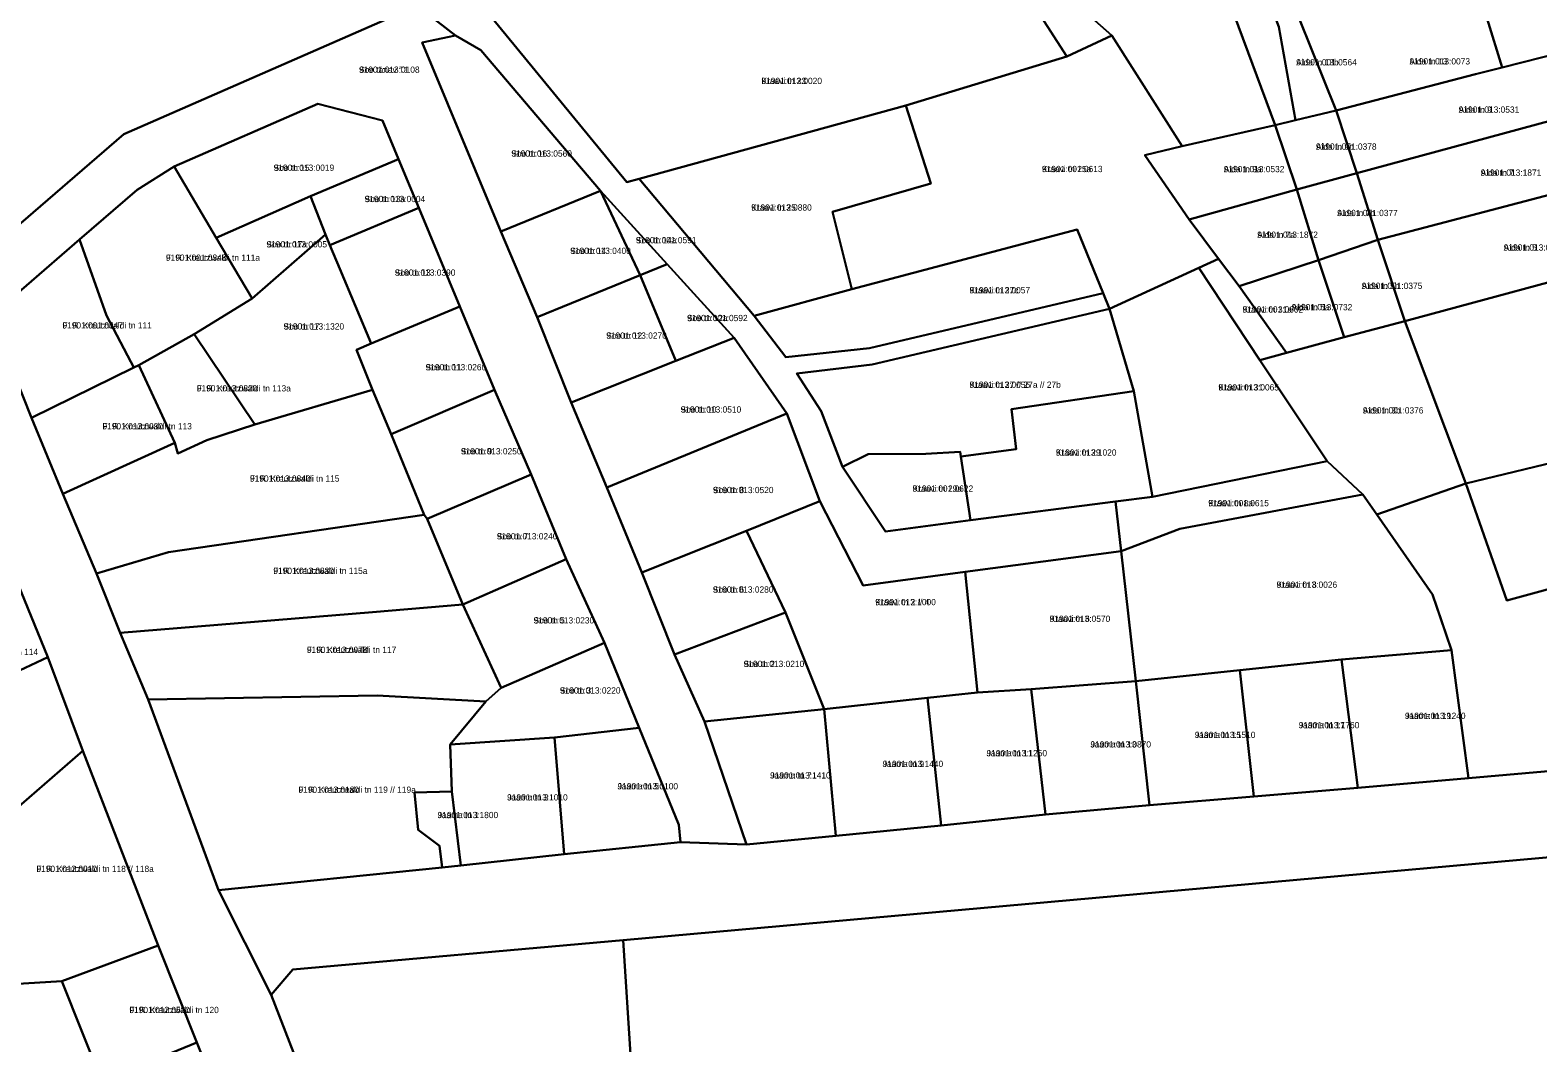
# Model space of a CAD drawing. Extents: x 675810 to 681273, y 6411190 to 6417565.
# Drawn here: x 678840.3 to 679201.2, y 6413542.7 to 6413785.2 of the extents above; entities that cross this region are included whole.
import ezdxf

# ---------------------------------------------------------------- set-up
doc = ezdxf.new("R2010")
doc.units = 0
for name, color, linetype in [('L_AADRESS', 7, 'Continuous'), ('PIIR', 7, 'Continuous'), ('TUNNUS', 7, 'Continuous')]:
    doc.layers.add(name, color=color, linetype=linetype)

msp = doc.modelspace()

# ---------------------------------------------------------------- linework, layer by layer
at = {"layer": 'PIIR'}
for points in [[(678826.29, 6413728.84), (678795.17, 6413816.56), (678828, 6413829.05), (678859.96, 6413845.39), (678877.6, 6413860.64), (678932.91, 6413791.06), (678862.71, 6413760.35)], [(679063.55, 6413813.47), (679076.05, 6413804.42), (679099.24, 6413783.96), (679088.47, 6413778.92), (679077.61, 6413795.82)], [(679076.05, 6413804.42), (679124.13, 6413800.75), (679138.31, 6413762.5), (679116.06, 6413757.41), (679099.24, 6413783.96)], [(679124.13, 6413800.75), (679133.81, 6413800.32), (679139.23, 6413785.98), (679143.23, 6413763.68), (679138.31, 6413762.5)], [(679139.17, 6413800.08), (679144.1, 6413788.04), (679152.9, 6413765.99), (679143.23, 6413763.68), (679139.23, 6413785.98), (679133.81, 6413800.32)], [(679139.17, 6413800.08), (679200.86, 6413799.83), (679207.07, 6413779.92), (679192.67, 6413776.28), (679189.1, 6413787.94), (679180.37, 6413787.89), (679144.1, 6413788.04)], [(678948, 6413791.61), (679001.31, 6413793.35), (679077.61, 6413795.82), (679088.47, 6413778.92), (679049.95, 6413767.16), (678986.06, 6413749.64), (678983.09, 6413748.82)], [(679144.1, 6413788.04), (679180.37, 6413787.89), (679189.1, 6413787.94), (679192.67, 6413776.28), (679186.28, 6413774.66), (679152.9, 6413765.99)], [(678976.85, 6413746.77), (678952.97, 6413737), (678934.1, 6413782.23), (678942.15, 6413783.91), (678948.14, 6413780.47)], [(679117.74, 6413739.91), (679124.79, 6413730.47), (679120.02, 6413728.32), (679098.68, 6413718.49), (679097.14, 6413722.24), (679090.92, 6413737.49), (679037.01, 6413723.19), (679032.32, 6413741.72), (679055.93, 6413748.54), (679049.95, 6413767.16), (679088.47, 6413778.92), (679099.24, 6413783.96), (679116.06, 6413757.41), (679107.12, 6413755.3)], [(679152.9, 6413765.99), (679186.28, 6413774.66), (679192.67, 6413776.28), (679207.07, 6413779.92), (679212.4, 6413765.71), (679157.89, 6413750.98)], [(678909.17, 6413767.57), (678924.61, 6413763.6), (678928.45, 6413754.37), (678907.43, 6413745.44), (678884.86, 6413735.51), (678874.73, 6413752.61)], [(678986.06, 6413749.64), (679049.95, 6413767.16), (679055.93, 6413748.54), (679032.32, 6413741.72), (679037.01, 6413723.19), (679013.58, 6413716.85)], [(679138.31, 6413762.5), (679143.23, 6413763.68), (679152.9, 6413765.99), (679157.89, 6413750.98), (679143.48, 6413747.11)], [(679212.4, 6413765.71), (679217.3, 6413749.31), (679162.87, 6413735.01), (679157.89, 6413750.98)], [(679143.48, 6413747.11), (679117.74, 6413739.91), (679107.12, 6413755.3), (679116.06, 6413757.41), (679138.31, 6413762.5)], [(678928.45, 6413754.37), (678933.3, 6413742.71), (678912.07, 6413733.74), (678911.01, 6413736.28), (678907.43, 6413745.44)], [(678858.59, 6413716.93), (678852.13, 6413735.1), (678865.9, 6413746.98), (678874.73, 6413752.61), (678884.86, 6413735.51), (678893.45, 6413720.95), (678879.58, 6413712.42), (678866.3, 6413705.02), (678865.15, 6413704.45), (678864.43, 6413705.82)], [(679143.48, 6413747.11), (679157.89, 6413750.98), (679162.87, 6413735.01), (679148.72, 6413730.16)], [(678976.85, 6413746.77), (678986.29, 6413726.59), (678961.65, 6413716.54), (678952.97, 6413737)], [(678986.29, 6413726.59), (678976.85, 6413746.77), (678992.77, 6413729.23)], [(679143.48, 6413747.11), (679148.72, 6413730.16), (679129.69, 6413723.9), (679124.79, 6413730.47), (679117.74, 6413739.91)], [(679162.87, 6413735.01), (679217.3, 6413749.31), (679223.07, 6413730.04), (679169.39, 6413715.58)], [(678907.43, 6413745.44), (678911.01, 6413736.28), (678893.45, 6413720.95), (678884.86, 6413735.51)], [(678921.91, 6413710.19), (678914.45, 6413728.04), (678912.07, 6413733.74), (678933.3, 6413742.71), (678943.12, 6413719.07)], [(678894.06, 6413690.79), (678879.58, 6413712.42), (678893.45, 6413720.95), (678911.01, 6413736.28), (678912.07, 6413733.74), (678914.45, 6413728.04), (678921.91, 6413710.19), (678918.45, 6413708.68), (678922.27, 6413699.08)], [(679013.58, 6413716.85), (679037.01, 6413723.19), (679090.92, 6413737.49), (679097.14, 6413722.24), (679041.18, 6413709.07), (679021.21, 6413706.91)], [(678840.61, 6413692.4), (678830.89, 6413716.75), (678852.13, 6413735.1), (678858.59, 6413716.93), (678864.43, 6413705.82), (678865.15, 6413704.45)], [(679148.72, 6413730.16), (679162.87, 6413735.01), (679169.39, 6413715.58), (679154.88, 6413711.69)], [(678986.29, 6413726.59), (678992.77, 6413729.23), (679008.79, 6413711.58), (678994.88, 6413706.06)], [(679120.02, 6413728.32), (679124.79, 6413730.47), (679129.69, 6413723.9), (679141.04, 6413707.94), (679134.68, 6413706.23)], [(679154.88, 6413711.69), (679141.04, 6413707.94), (679129.69, 6413723.9), (679148.72, 6413730.16)], [(679223.07, 6413730.04), (679235.52, 6413689.16), (679183.96, 6413676.67), (679169.39, 6413715.58)], [(678969.79, 6413696.09), (678961.65, 6413716.54), (678986.29, 6413726.59), (678994.88, 6413706.06)], [(679120.02, 6413728.32), (679134.68, 6413706.23), (679150.77, 6413682), (679108.94, 6413673.45), (679104.53, 6413698.78), (679098.68, 6413718.49)], [(678951.45, 6413699.09), (678926.73, 6413688.45), (678922.27, 6413699.08), (678918.45, 6413708.68), (678921.91, 6413710.19), (678943.12, 6413719.07)], [(679023.81, 6413703.04), (679041.85, 6413705.13), (679098.68, 6413718.49), (679104.53, 6413698.78), (679075.22, 6413694.49), (679076.29, 6413684.93), (679063.09, 6413683.16), (679062.94, 6413684.22), (679054.68, 6413683.75), (679040.92, 6413683.71), (679034.72, 6413680.68), (679029.61, 6413694.02)], [(679154.88, 6413711.69), (679169.39, 6413715.58), (679183.96, 6413676.67), (679162.66, 6413669.25), (679159.3, 6413674.02), (679150.77, 6413682), (679134.68, 6413706.23), (679141.04, 6413707.94)], [(678874.95, 6413686.38), (678866.3, 6413705.02), (678879.58, 6413712.42), (678894.06, 6413690.79), (678882.56, 6413687.02), (678875.62, 6413683.83)], [(679008.79, 6413711.58), (679021.39, 6413693.4), (678978.31, 6413675.73), (678969.79, 6413696.09), (678994.88, 6413706.06)], [(678840.61, 6413692.4), (678865.15, 6413704.45), (678866.3, 6413705.02), (678874.95, 6413686.38), (678848.13, 6413674.24)], [(678856.15, 6413655.14), (678848.13, 6413674.24), (678874.95, 6413686.38), (678875.62, 6413683.83), (678882.56, 6413687.02), (678894.06, 6413690.79), (678922.27, 6413699.08), (678926.73, 6413688.45), (678934.63, 6413669.18), (678873.41, 6413660.22)], [(678935.36, 6413668.19), (678934.63, 6413669.18), (678926.73, 6413688.45), (678951.45, 6413699.09), (678960.19, 6413678.87)], [(679065.38, 6413667.91), (679063.09, 6413683.16), (679076.29, 6413684.93), (679075.22, 6413694.49), (679104.53, 6413698.78), (679108.94, 6413673.45), (679100.14, 6413672.34)], [(678978.31, 6413675.73), (679021.39, 6413693.4), (679029.36, 6413672.42), (679011.74, 6413665.37), (678986.68, 6413655.34)], [(679215.96, 6413660.7), (679217.77, 6413655.18), (679193.81, 6413648.7), (679183.96, 6413676.67), (679235.52, 6413689.16), (679243.75, 6413664.08)], [(679065.38, 6413667.91), (679045.07, 6413665.2), (679034.72, 6413680.68), (679040.92, 6413683.71), (679054.68, 6413683.75), (679062.94, 6413684.22), (679063.09, 6413683.16)], [(679115.48, 6413665.83), (679101.49, 6413660.46), (679100.14, 6413672.34), (679108.94, 6413673.45), (679150.77, 6413682), (679159.3, 6413674.02)], [(678960.19, 6413678.87), (678968.58, 6413658.56), (678943.85, 6413647.72), (678935.36, 6413668.19)], [(679193.81, 6413648.7), (679217.77, 6413655.18), (679215.96, 6413660.7), (679243.75, 6413664.08), (679249.72, 6413644.17), (679220.83, 6413641.03), (679228.23, 6413609.96), (679184.59, 6413606.09), (679180.54, 6413636.74), (679177.8, 6413644.75), (679175.98, 6413650.08), (679162.66, 6413669.25), (679183.96, 6413676.67)], [(679039.72, 6413652.22), (679064.09, 6413655.49), (679067.03, 6413626.65), (679055.08, 6413625.34), (679030.33, 6413622.63), (679021.13, 6413645.8), (679011.74, 6413665.37), (679029.36, 6413672.42)], [(679101.49, 6413660.46), (679115.48, 6413665.83), (679159.3, 6413674.02), (679162.66, 6413669.25), (679175.98, 6413650.08), (679180.54, 6413636.74), (679154.21, 6413634.56), (679129.83, 6413632), (679105, 6413629.38)], [(678856.15, 6413655.14), (678873.41, 6413660.22), (678934.63, 6413669.18), (678935.36, 6413668.19), (678943.85, 6413647.72), (678922.25, 6413645.87), (678861.84, 6413640.88)], [(678986.68, 6413655.34), (679011.74, 6413665.37), (679021.13, 6413645.8), (678994.52, 6413635.71)], [(679105, 6413629.38), (679079.92, 6413627.45), (679067.03, 6413626.65), (679064.09, 6413655.49), (679101.49, 6413660.46)], [(678943.85, 6413647.72), (678968.58, 6413658.56), (678977.75, 6413638.55), (678953.06, 6413627.76)], [(678796.59, 6413635.26), (678836.58, 6413654.64), (678844.5, 6413635.09), (678805.1, 6413616.54)], [(678943.85, 6413647.72), (678953.06, 6413627.76), (678949.36, 6413624.48), (678923.35, 6413625.95), (678868.51, 6413624.93), (678861.84, 6413640.88), (678922.25, 6413645.87)], [(678994.52, 6413635.71), (679021.13, 6413645.8), (679030.33, 6413622.63), (679001.7, 6413619.65)], [(678940.81, 6413614.2), (678949.36, 6413624.48), (678953.06, 6413627.76), (678977.75, 6413638.55), (678986.11, 6413618.2), (678965.8, 6413615.87)], [(678852.91, 6413612.7), (678810.65, 6413575.98), (678800.26, 6413567.02), (678763.72, 6413543), (678719.84, 6413576.34), (678764.11, 6413597.24), (678805.1, 6413616.54), (678844.5, 6413635.09)], [(679129.83, 6413632), (679154.21, 6413634.56), (679158.11, 6413603.82), (679133.18, 6413601.75)], [(679158.11, 6413603.82), (679154.21, 6413634.56), (679180.54, 6413636.74), (679184.59, 6413606.09)], [(679105, 6413629.38), (679129.83, 6413632), (679133.18, 6413601.75), (679108.27, 6413599.69)], [(679058.38, 6413594.81), (679055.08, 6413625.34), (679067.03, 6413626.65), (679079.92, 6413627.45), (679083.36, 6413597.41)], [(679105, 6413629.38), (679108.27, 6413599.69), (679083.36, 6413597.41), (679079.92, 6413627.45)], [(678868.51, 6413624.93), (678923.35, 6413625.95), (678949.36, 6413624.48), (678940.81, 6413614.2), (678941.27, 6413602.94), (678932.27, 6413602.69), (678933.21, 6413593.73), (678938.27, 6413589.92), (678938.95, 6413584.75), (678885.41, 6413579.27)], [(679055.08, 6413625.34), (679058.38, 6413594.81), (679033.13, 6413592.31), (679030.33, 6413622.63)], [(679001.7, 6413619.65), (679030.33, 6413622.63), (679033.13, 6413592.31), (679011.76, 6413590.25)], [(678965.8, 6413615.87), (678986.11, 6413618.2), (678995.58, 6413594.92), (678995.96, 6413590.79), (678968.13, 6413587.95)], [(678943.38, 6413585.24), (678941.27, 6413602.94), (678940.81, 6413614.2), (678965.8, 6413615.87), (678968.13, 6413587.95)], [(678870.9, 6413566.06), (678847.87, 6413557.53), (678800.48, 6413554.63), (678800.26, 6413567.02), (678810.65, 6413575.98), (678852.91, 6413612.7)], [(678665.74, 6413606.8), (678695.3, 6413600.11), (678714.53, 6413595.62), (678719.84, 6413576.34), (678763.72, 6413543), (678800.26, 6413567.02), (678800.48, 6413554.63), (678847.87, 6413557.53), (678857.44, 6413533.51), (678880.23, 6413542.83), (678888.05, 6413523.44), (678805.9, 6413512.49), (678631.5, 6413551.06), (678639.57, 6413556.01), (678656.18, 6413588.23)], [(678932.27, 6413602.69), (678941.27, 6413602.94), (678943.38, 6413585.24), (678938.95, 6413584.75), (678938.27, 6413589.92), (678933.21, 6413593.73)], [(678870.9, 6413566.06), (678880.23, 6413542.83), (678857.44, 6413533.51), (678847.87, 6413557.53)], [(678914.04, 6413512.86), (678897.96, 6413554.23), (678903.14, 6413560.3), (678982.22, 6413567.37), (678984.06, 6413538.75), (678963.55, 6413537.52), (678965.52, 6413517.11)]]:
    msp.add_lwpolyline(points, close=True, dxfattribs=at)
for points in [[(678826.29, 6413728.84), (678862.71, 6413760.35), (678932.91, 6413791.06), (678942.15, 6413783.91), (678934.1, 6413782.23), (678952.97, 6413737), (678961.65, 6413716.54), (678969.79, 6413696.09), (678978.31, 6413675.73), (678986.68, 6413655.34), (678994.52, 6413635.71), (679001.7, 6413619.65), (679011.76, 6413590.25), (678995.96, 6413590.79), (678995.58, 6413594.92), (678986.11, 6413618.2), (678977.75, 6413638.55), (678968.58, 6413658.56), (678960.19, 6413678.87), (678951.45, 6413699.09), (678943.12, 6413719.07), (678933.3, 6413742.71), (678928.45, 6413754.37), (678924.61, 6413763.6), (678909.17, 6413767.57), (678874.73, 6413752.61), (678865.9, 6413746.98), (678852.13, 6413735.1), (678830.89, 6413716.75)], [(678948, 6413791.61), (678983.09, 6413748.82), (678986.06, 6413749.64), (679013.58, 6413716.85), (679021.21, 6413706.91), (679041.18, 6413709.07), (679097.14, 6413722.24), (679098.68, 6413718.49), (679041.85, 6413705.13), (679023.81, 6413703.04), (679029.61, 6413694.02), (679034.72, 6413680.68), (679045.07, 6413665.2), (679065.38, 6413667.91), (679100.14, 6413672.34), (679101.49, 6413660.46), (679064.09, 6413655.49), (679039.72, 6413652.22), (679029.36, 6413672.42), (679021.39, 6413693.4), (679008.79, 6413711.58), (678992.77, 6413729.23), (678976.85, 6413746.77), (678948.14, 6413780.47), (678942.15, 6413783.91), (678932.91, 6413791.06)], [(678830.89, 6413716.75), (678840.61, 6413692.4), (678848.13, 6413674.24), (678856.15, 6413655.14), (678861.84, 6413640.88), (678868.51, 6413624.93), (678885.41, 6413579.27), (678897.96, 6413554.23), (678914.04, 6413512.86)], [(678888.05, 6413523.44), (678880.23, 6413542.83), (678870.9, 6413566.06), (678852.91, 6413612.7), (678844.5, 6413635.09), (678836.58, 6413654.64)], [(679314.57, 6413597.1), (678982.22, 6413567.37), (678903.14, 6413560.3), (678897.96, 6413554.23), (678885.41, 6413579.27), (678938.95, 6413584.75), (678943.38, 6413585.24), (678968.13, 6413587.95), (678995.96, 6413590.79), (679011.76, 6413590.25), (679033.13, 6413592.31), (679058.38, 6413594.81), (679083.36, 6413597.41), (679108.27, 6413599.69), (679133.18, 6413601.75), (679158.11, 6413603.82), (679184.59, 6413606.09), (679228.23, 6413609.96)], [(678984.06, 6413538.75), (678982.22, 6413567.37), (679314.57, 6413597.1), (679330.12, 6413556.83), (679423.93, 6413564.22)]]:
    msp.add_lwpolyline(points, dxfattribs=at)

# ---------------------------------------------------------------- texts
at = {"layer": 'L_AADRESS'}
for s, p in [('Soo tänav T1', (678919.02, 6413775.01)), ('Aida tn 13b', (679143.36, 6413776.78)), ('Aida tn 13', (679170.47, 6413777.01)), ('Kraavi tn 23', (679015.34, 6413772.32)), ('Aida tn 9', (679182.26, 6413765.45)), ('Aida tn 9b', (679148.1, 6413756.6)), ('Soo tn 16', (678955.48, 6413754.94)), ('Soo tn 15', (678898.58, 6413751.54)), ('Kraavi tn 25a', (679082.5, 6413751.23)), ('Aida tn 9a', (679126.03, 6413751.21)), ('Aida tn 7', (679187.53, 6413750.36)), ('Soo tn 13a', (678920.36, 6413744.05)), ('Kraavi tn 25', (679012.89, 6413742.01)), ('Aida tn 7b', (679153.17, 6413740.7)), ('Soo tn 14a', (678985.3, 6413734.2)), ('Aida tn 7a', (679134.05, 6413735.5)), ('Soo tn 17a', (678896.85, 6413733.2)), ('Soo tn 14', (678969.58, 6413731.65)), ('Aida tn 5', (679193.04, 6413732.44)), ('F. R. Kreutzwaldi tn 111a', (678872.79, 6413730)), ('Soo tn 13', (678927.59, 6413726.43)), ('Aida tn 5b', (679159.05, 6413723.26)), ('Kraavi tn 27c', (679065.16, 6413722.2)), ('Kraavi tn 31a', (679130.53, 6413717.6)), ('Aida tn 5a', (679142.29, 6413718.16)), ('F. R. Kreutzwaldi tn 111', (678848.02, 6413713.79)), ('Soo tn 17', (678900.95, 6413713.54)), ('Soo tn 12a', (678997.54, 6413715.55)), ('Soo tn 12', (678978.2, 6413711.34)), ('Soo tn 11', (678934.96, 6413703.76)), ('F. R. Kreutzwaldi tn 113a', (678880.18, 6413698.72)), ('Kraavi tn 27 // 27a // 27b', (679065.16, 6413699.58)), ('Kraavi tn 31', (679124.73, 6413698.95)), ('Soo tn 10', (678996.01, 6413693.65)), ('Aida tn 3b', (679159.32, 6413693.44)), ('F. R. Kreutzwaldi tn 113', (678857.6, 6413689.63)), ('Soo tn 9', (678943.42, 6413683.64)), ('Kraavi tn 29', (679085.84, 6413683.35)), ('F. R. Kreutzwaldi tn 115', (678892.92, 6413677.11)), ('Soo tn 8', (679003.74, 6413674.37)), ('Kraavi tn 29a', (679051.54, 6413674.71)), ('Kraavi tn 8a', (679122.32, 6413671.23)), ('Soo tn 7', (678952.01, 6413663.29)), ('F. R. Kreutzwaldi tn 115a', (678898.51, 6413655.03)), ('Kraavi tn 8', (679138.67, 6413651.7)), ('Soo tn 6', (679003.73, 6413650.54)), ('Kraavi tn 2 // 4', (679042.6, 6413647.53)), ('Soo tn 5', (678960.8, 6413643.16)), ('Kraavi tn 6', (679084.35, 6413643.55)), ('F. R. Kreutzwaldi tn 114', (678820.78, 6413635.59)), ('F. R. Kreutzwaldi tn 117', (678906.53, 6413636.1)), ('Soo tn 2', (679011.09, 6413632.73)), ('Soo tn 3', (678967.12, 6413626.38)), ('Jaama tn 19', (679169.4, 6413620.3)), ('Jaama tn 15', (679119.09, 6413615.73)), ('Jaama tn 17', (679143.97, 6413618.07)), ('Jaama tn 11', (679069.22, 6413611.36)), ('Jaama tn 13', (679094.1, 6413613.47)), ('Jaama tn 9', (679044.36, 6413608.79)), ('Jaama tn 7', (679017.42, 6413606.04)), ('F. R. Kreutzwaldi tn 119 // 119a', (678904.52, 6413602.61)), ('Jaama tn 3', (678954.47, 6413600.78)), ('Jaama tn 5', (678980.88, 6413603.43)), ('Jaama tn 1', (678937.83, 6413596.55)), ('F. R. Kreutzwaldi tn 118 // 118a', (678841.8, 6413583.66)), ('F. R. Kreutzwaldi tn 120', (678864.05, 6413549.87))]:
    msp.add_text(s, height=1.5, dxfattribs=at).set_placement(p)
at = {"layer": 'TUNNUS'}
for s, p in [('91901:013:0108', (678919.02, 6413775.01)), ('91901:001:0564', (679143.36, 6413776.78)), ('91901:013:0073', (679170.47, 6413777.01)), ('91901:013:0020', (679015.34, 6413772.32)), ('91901:013:0531', (679182.26, 6413765.45)), ('91901:001:0378', (679148.1, 6413756.6)), ('91901:013:0560', (678955.48, 6413754.94)), ('91901:013:0019', (678898.58, 6413751.54)), ('91901:001:0613', (679082.5, 6413751.23)), ('91901:013:0532', (679126.03, 6413751.21)), ('91901:013:1871', (679187.53, 6413750.36)), ('91901:013:0004', (678920.36, 6413744.05)), ('91901:013:0880', (679012.89, 6413742.01)), ('91901:001:0377', (679153.17, 6413740.7)), ('91901:001:0591', (678985.3, 6413734.2)), ('91901:013:1872', (679134.05, 6413735.5)), ('91901:013:0005', (678896.85, 6413733.2)), ('91901:013:0400', (678969.58, 6413731.65)), ('91901:013:0731', (679193.04, 6413732.44)), ('91901:001:0348', (678872.79, 6413730)), ('91901:013:0390', (678927.59, 6413726.43)), ('91901:001:0375', (679159.05, 6413723.26)), ('91901:013:0057', (679065.16, 6413722.2)), ('91901:001:0602', (679130.53, 6413717.6)), ('91901:013:0732', (679142.29, 6413718.16)), ('91901:001:0347', (678848.02, 6413713.79)), ('91901:013:1320', (678900.95, 6413713.54)), ('91901:001:0592', (678997.54, 6413715.55)), ('91901:013:0270', (678978.2, 6413711.34)), ('91901:013:0260', (678934.96, 6413703.76)), ('91901:013:0820', (678880.18, 6413698.72)), ('91901:013:0056', (679065.16, 6413699.58)), ('91901:013:0065', (679124.73, 6413698.95)), ('91901:013:0510', (678996.01, 6413693.65)), ('91901:001:0376', (679159.32, 6413693.44)), ('91901:013:0030', (678857.6, 6413689.63)), ('91901:013:0250', (678943.42, 6413683.64)), ('91901:013:1020', (679085.84, 6413683.35)), ('91901:013:0840', (678892.92, 6413677.11)), ('91901:013:0520', (679003.74, 6413674.37)), ('91901:001:0622', (679051.54, 6413674.71)), ('91901:001:0615', (679122.32, 6413671.23)), ('91901:013:0240', (678952.01, 6413663.29)), ('91901:013:0830', (678898.51, 6413655.03)), ('91901:013:0026', (679138.67, 6413651.7)), ('91901:013:0280', (679003.73, 6413650.54)), ('91901:013:1000', (679042.6, 6413647.53)), ('91901:013:0230', (678960.8, 6413643.16)), ('91901:013:0570', (679084.35, 6413643.55)), ('91901:013:0078', (678906.53, 6413636.1)), ('91901:013:0210', (679011.09, 6413632.73)), ('91901:013:0220', (678967.12, 6413626.38)), ('91901:013:1240', (679169.4, 6413620.3)), ('91901:013:1510', (679119.09, 6413615.73)), ('91901:013:1760', (679143.97, 6413618.07)), ('91901:013:1250', (679069.22, 6413611.36)), ('91901:013:0870', (679094.1, 6413613.47)), ('91901:013:1440', (679044.36, 6413608.79)), ('91901:013:1410', (679017.42, 6413606.04)), ('91901:013:0180', (678904.52, 6413602.61)), ('91901:013:1010', (678954.47, 6413600.78)), ('91901:013:0100', (678980.88, 6413603.43)), ('91901:013:1800', (678937.83, 6413596.55)), ('91901:012:0010', (678841.8, 6413583.66)), ('91901:012:0520', (678864.05, 6413549.87))]:
    msp.add_text(s, height=1.5, dxfattribs=at).set_placement(p)

doc.saveas('drawing.dxf')
